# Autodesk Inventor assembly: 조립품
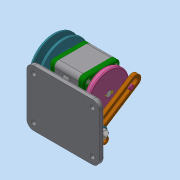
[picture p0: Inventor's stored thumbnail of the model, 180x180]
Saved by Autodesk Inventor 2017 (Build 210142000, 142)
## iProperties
Part Number: 조립품
Material: 일반
Document SubType Name: Assembly
Designer: mrc
Author: mrc
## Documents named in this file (19)
- C:\Users\mrc\Desktop\601106V1032\조립품.iam
- C:\Users\mrc\Desktop\601106V1032\V-벨트풀리.ipt
- C:\Users\mrc\Desktop\601106V1032\너트 M8.ipt
- C:\Users\mrc\Desktop\601106V1032\너트 M10x1.ipt
- C:\Users\mrc\Desktop\601106V1032\돌림판.ipt
- C:\Users\mrc\Desktop\601106V1032\멈춤나사 M3x5.ipt
- C:\Users\mrc\Desktop\601106V1032\베어링 6004.ipt
- C:\Users\mrc\Desktop\601106V1032\본체.ipt
- C:\Users\mrc\Desktop\601106V1032\볼트 M4.ipt
- C:\Users\mrc\Desktop\601106V1032\오일 실 17 30 5.ipt
- C:\Users\mrc\Desktop\601106V1032\와셔 8x15.5.ipt
- C:\Users\mrc\Desktop\601106V1032\축.ipt
- C:\Users\mrc\Desktop\601106V1032\커버.ipt
- C:\Users\mrc\Desktop\601106V1032\크랭크.ipt
- C:\Users\mrc\Desktop\601106V1032\키 4 x 4 x 8.ipt
- C:\Users\mrc\Desktop\601106V1032\키 5 x 5 x 12.ipt
- C:\Users\mrc\Desktop\601106V1032\핀 3 x 8.ipt
- C:\Users\mrc\Desktop\601106V1032\힌지 축.ipt
- C:\Users\mrc\Desktop\601106V1032\힌지.ipt
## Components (3 placed, 2 different names)
1. V-벨트풀리:1
2. 핀 3 x 8:1 — 플러쉬:2
3. 핀 3 x 8:2 — 플러쉬:3
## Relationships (2: Flush 2)
- 플러쉬:2 [Flush]: 핀 3 x 8:1
- 플러쉬:3 [Flush]: 핀 3 x 8:2
